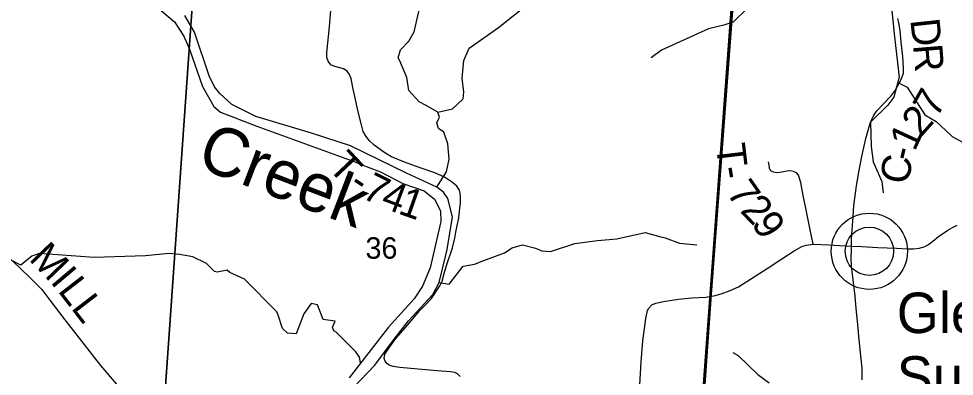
# Model space of a CAD drawing. Extents: x 1878108 to 2183446, y 146837 to 508383.
# Drawn here: x 2009743 to 2019382, y 343657 to 347340 of the extents above; entities that cross this region are included whole.
import ezdxf

# ---------------------------------------------------------------- set-up
doc = ezdxf.new("R2010")
doc.units = 0
for name, color, linetype in [('GM_X_County_Road', 7, 'Continuous'), ('GM_X_County_Road_Text', 7, 'Continuous'), ('GM_X_Major_River', 7, 'Continuous'), ('GM_X_Major_River_Text', 7, 'Continuous'), ('GM_X_Minor_River', 7, 'Continuous'), ('GM_X_Section', 7, 'Continuous'), ('GM_X_Section_Text', 7, 'Continuous'), ('GM_X_Township', 7, 'Continuous'), ('GM_X_Township_Road', 7, 'Continuous'), ('GM_X_Township_Road_Text', 7, 'Continuous'), ('GM_X_Unincorporated', 7, 'Continuous'), ('GM_X_Unincorporated_Location', 7, 'Continuous'), ('GM_X_Unincorporated_Text', 7, 'Continuous')]:
    doc.layers.add(name, color=color, linetype=linetype)

msp = doc.modelspace()

# ---------------------------------------------------------------- linework, layer by layer
at = {"layer": 'GM_X_County_Road'}
for points in [[(2018530.7, 346300.4), (2018548.9, 346340.2), (2018582.5, 346390.8), (2018650, 346461.6), (2018730.6, 346546.7), (2018771, 346602.2), (2018835.3, 346714.4), (2018858.1, 346779.8), (2018859.2, 346832.1), (2018852.7, 346949.7), (2018835.3, 347099), (2018823.3, 347215.6), (2018811.3, 347300.6), (2018799.3, 347342)], [(2018324.2, 344996.4), (2018323.2, 345071.3), (2018339.5, 345301.2), (2018347.1, 345415.6), (2018375.5, 345619.4), (2018398.3, 345761), (2018429.9, 345920.1), (2018470.3, 346107.5), (2018519.3, 346275.3), (2018530.7, 346300.4)], [(2018324.2, 344996.4), (2018427.8, 344992.8), (2018594.5, 344985.2), (2018787.3, 344977.6), (2018899.6, 344971), (2018961.7, 344970), (2019019.7, 344975.4), (2019072.5, 344991.2), (2019115.1, 345013.6), (2019161.2, 345048.4), (2019220.7, 345095.6), (2019315, 345160.7), (2019364.4, 345191), (2019410.4, 345212.3)], [(2016901.9, 344485.5), (2016904.6, 344486), (2016980.9, 344506.2), (2017071.8, 344539.8), (2017159.4, 344579.1), (2017463.7, 344774.5), (2017606.2, 344867.7), (2017733.7, 344949.3), (2017810, 344995), (2017856.8, 345008.1), (2017926.5, 345016.8), (2018088.9, 345012.4), (2018197.9, 345003.5), (2018324.2, 344996.4)], [(2009594.6, 344923.9), (2009753.8, 344775.2), (2009864.7, 344667.6), (2009981.3, 344549.9), (2010065.1, 344440.1), (2010219, 344237.5), (2010340.1, 344081.3), (2010523.5, 343845.9), (2010584.6, 343767.8), (2010746.5, 343578.8), (2010929.9, 343384.1), (2010998.9, 343310.5), (2011047.6, 343269.7), (2011211.7, 343195), (2011652, 343011.7), (2011765.8, 342960.5)], [(2016135.5, 343447.5), (2016149, 343684.4), (2016155.7, 343806.7), (2016171.5, 344023.4), (2016202.9, 344252.4), (2016219.7, 344334.4), (2016235.4, 344360.2), (2016264.6, 344391.6), (2016307.3, 344411.9), (2016385.9, 344428.7), (2016541.9, 344452.3), (2016677.8, 344464.6), (2016823.7, 344472.5), (2016875, 344481), (2016901.9, 344485.5)]]:
    msp.add_lwpolyline(points, dxfattribs=at)
at = {"layer": 'GM_X_Major_River'}
for points in [[(2010888.7, 347700.8), (2011346.8, 347309.5), (2011442.9, 347159.5), (2011503.1, 347027.4), (2011635.6, 346641.1), (2011753.8, 346437), (2011821.8, 346377.1), (2012195.6, 346232), (2013214.9, 345862.6), (2013276.8, 345836.7), (2013468.7, 345763.2), (2013698.6, 345643.7), (2013918.5, 345568.3), (2014026.5, 345480.5), (2014088.6, 345360.4), (2014092.8, 345250.2), (2013981.8, 344772.9), (2013904.2, 344584.3), (2013816.6, 344455.8), (2013553.4, 344162.4), (2013146.9, 343640.1)], [(2013119.3, 343467.7), (2013412.3, 343773.2), (2013609.6, 344040.3), (2013757.1, 344227.1), (2014008.2, 344498.5), (2014073.9, 344622.9), (2014139.4, 344889.6), (2014157.2, 344961.8), (2014212.5, 345300.7), (2014164.3, 345488.9), (2014118.2, 345554.9), (2014050.2, 345604.8), (2013738.4, 345750), (2013162.6, 346030.7), (2012758.9, 346159.7), (2012185.4, 346334.2), (2011939.5, 346455.7), (2011813.5, 346571.5), (2011759.4, 346637.5), (2011705.3, 346753.5), (2011552.7, 347199.9), (2011454.5, 347374)]]:
    msp.add_lwpolyline(points, dxfattribs=at)
at = {"layer": 'GM_X_Minor_River'}
for points in [[(2018025, 348200.1), (2017916.9, 347951.6), (2017891.1, 347835.4), (2017839.3, 347749.2), (2017611.7, 347612.6), (2017250.2, 347447.7), (2017102.6, 347303.2), (2017008.7, 347275), (2016850.9, 347234.7), (2016365.7, 347017.5), (2016257.9, 346937.2)], [(2014060.9, 346378.4), (2014210.7, 346412.7), (2014320.5, 346515.1), (2014330.4, 346583.1), (2014312.2, 346729.3), (2014328, 346909.5), (2014383.8, 347037.8), (2014687.2, 347250.6), (2015038.5, 347535.6), (2015148.3, 347666), (2015295.7, 348036.8)], [(2014050.2, 345604.8), (2014149.5, 345761.8), (2014179.3, 345892), (2014163.1, 346052.2), (2014121, 346172.3), (2014067.1, 346208.2), (2014051, 346266.2), (2014076.9, 346326.4), (2014060.9, 346378.4), (2013934.9, 346448.2), (2013867, 346484.2), (2013761, 346600.1), (2013742.8, 346734.2), (2013670.7, 346906.3), (2013652.7, 346938.3), (2013674.6, 347020.5), (2013760.4, 347108.7), (2013818.2, 347205), (2013865.9, 347413.3), (2013873.9, 347463.4), (2013883.6, 347671.6), (2013921.4, 347827.9)], [(2018627.8, 347657.6), (2018728.5, 347522.6), (2018764.9, 347154.2), (2018813.3, 346739.8), (2018759.6, 346533.5), (2018697.8, 346451.2), (2018518.2, 346274.7), (2018526.4, 346024.4), (2018546.6, 345866.3), (2018634.7, 345662.2), (2018648.8, 345546.1)], [(2018798.5, 346682.9), (2018895.4, 346633.8), (2019077.5, 346351.8), (2019193.4, 346280), (2019293.4, 346188.1), (2019359.4, 346126.1), (2019543.3, 346026.3), (2019723.4, 345774.4), (2019785.4, 345730.4), (2019815.4, 345702.5)], [(2014074.2, 344624), (2014176.7, 344606.6), (2014320.4, 344791.1), (2014440.2, 344813.3), (2014534.1, 344851.5), (2014747.8, 344928), (2014827.6, 344980.2), (2014933.5, 345012.5), (2015067.4, 344976.7), (2015131.3, 344950.8), (2015221.2, 344942.9), (2015470.9, 345025.5), (2015706.6, 345056), (2015906.3, 345074.4), (2016196, 345139), (2016359.8, 345095.2), (2016401.8, 345083.3), (2016549.7, 345029.5), (2016729.5, 345011.8)], [(2013265.4, 343795.9), (2013252.5, 343854), (2013216.5, 343910), (2013012.5, 344111.9), (2012988.5, 344123.8), (2012976.5, 344161.9), (2013002.4, 344224), (2012878.5, 344241.8), (2012822.4, 344393.8), (2012756.5, 344405.7), (2012678.7, 344299.5), (2012601, 344093.1), (2012511.1, 344102.9), (2012461.1, 344150.9), (2012417, 344287), (2012402.9, 344321), (2012068.9, 344658.7), (2011919, 344724.5), (2011889, 344750.5), (2011789.1, 344728.3), (2011761.2, 344736.2), (2011679.2, 344818.1), (2011537.2, 344888), (2011399.4, 344911.7), (2011291.5, 344923.5), (2011049.8, 344897.1), (2010520.3, 344882.1), (2009954.9, 344921), (2009877, 344894.9), (2009805.1, 344836.7), (2009763.2, 344800.6), (2009535.3, 344918.3)], [(2017101.6, 343900.5), (2017153.8, 343870.5), (2017358.5, 343674.5), (2017472.9, 343588.5)]]:
    msp.add_lwpolyline(points, dxfattribs=at)
at = {"layer": 'GM_X_Section'}
for points in [[(2011587.2, 348298.2), (2011214.3, 342968.4), (2006158.5, 343339.8), (2005874.4, 343365.2), (2006273.3, 348657.1)], [(2017121.1, 347933.9), (2017107.5, 347769.8), (2016724.2, 342600), (2011392.3, 342956.8), (2011214.3, 342968.4), (2011587.2, 348298.2)], [(2022491.3, 347433.1), (2022076.7, 341977.1), (2016695, 342231.8), (2016724.2, 342600), (2017107.5, 347769.8)]]:
    msp.add_lwpolyline(points, close=True, dxfattribs=at)
at = {"layer": 'GM_X_Township'}
for points in [[(2022085.4, 341976.5), (2018357.7, 342153.1), (2017167.6, 342204.4), (2016711.2, 342233), (2016735.7, 342465.3), (2016771.3, 342980.5), (2016876.3, 344500.5), (2017298, 350114.1), (2017363.4, 350984.7), (2017639.3, 354834.1), (2017696.9, 355615), (2017915.9, 358580.9), (2018284.3, 364566.1), (2018295.1, 364714.1), (2018544, 369044.3), (2019393.9, 369074.7)], [(2017298, 350114.1), (2016876.3, 344500.5), (2016771.3, 342980.5), (2016735.7, 342465.3), (2014090.7, 342780.8), (2012240.2, 342898.1), (2008693, 343157.7), (2004354.1, 343457.5), (2003141.6, 343548.2), (2000896.9, 343716.1), (1999693.4, 343807.9), (1997660.6, 343962.9), (1995715.1, 344111.2), (1994970.8, 344177.4), (1990310.6, 344542.4), (1989690.7, 344598.5), (1988327.1, 344706.4), (1984472.4, 345011.3), (1984423, 345015.2), (1984436.4, 345172.5), (1984507.3, 345999.8), (1984847.2, 350030.1)]]:
    msp.add_lwpolyline(points, dxfattribs=at)
at = {"layer": 'GM_X_Township_Road'}
for points in [[(2014292.4, 343655.4), (2014263.8, 343684), (2014235.2, 343695.6), (2014190.6, 343703.6), (2014053.9, 343712.6), (2013821.6, 343734), (2013669.7, 343749.2), (2013600.1, 343759), (2013559, 343771.5), (2013536.6, 343789.4), (2013517.7, 343813.3), (2013508, 343842.1), (2013515.2, 343885.9), (2013553.6, 343941.3), (2013590.2, 343994.9), (2013632.2, 344048.5), (2013748.4, 344185.1), (2013874.3, 344335.2), (2013927.9, 344387.9), (2013996.7, 344456.7), (2014079.8, 344589.8), (2014104.2, 344635.3), (2014127.7, 344717), (2014153.9, 344808.7), (2014212, 344979.3), (2014236.7, 345079.1), (2014246.8, 345142.8), (2014259.3, 345209.8), (2014278.1, 345287.5), (2014285.3, 345359), (2014295.1, 345444.8), (2014295.1, 345502.8), (2014291.5, 345543), (2014282.6, 345572.5), (2014256.7, 345614.5), (2014212.9, 345654.7), (2014129.8, 345707.4), (2014028.9, 345751.2), (2013869.9, 345807.5), (2013717.1, 345861.1), (2013584, 345917.3), (2013514.3, 345958.4), (2013404.4, 346037), (2013353.5, 346087.1), (2013315.1, 346136.2), (2013291, 346178.2), (2013274, 346248.8), (2013238.3, 346394.4), (2013213.2, 346507.8), (2013186.4, 346630.2), (2013169.5, 346724), (2013149.8, 346766.9), (2013128.4, 346798.2), (2013090, 346822.3), (2012999.7, 346848.2), (2012958.6, 346864.3), (2012930.9, 346901.8), (2012917.5, 346941.1), (2012915.8, 346993.8), (2012944.3, 347255.6), (2012961.3, 347469.1)], [(2017926.5, 345016.8), (2017893.7, 345183.1), (2017851, 345389.7), (2017826.3, 345517.7), (2017800.5, 345654.7), (2017778, 345727.6), (2017756.7, 345753.5), (2017724.1, 345768.1), (2017694.9, 345772.6), (2017657.9, 345770.3), (2017604, 345761.3), (2017552.4, 345752.3), (2017518.7, 345758), (2017491.7, 345772.6), (2017478.3, 345796.1), (2017474.9, 345834.3), (2017469.3, 345864.6)], [(2018433.5, 343621.2), (2018432.3, 343741.1), (2018419.4, 343868), (2018398.2, 344065.5), (2018391, 344157), (2018371.9, 344356.8), (2018361.3, 344484), (2018340.6, 344650.7), (2018323.2, 344792.4), (2018318.8, 344876.3), (2018323.2, 344954.7), (2018324.2, 344996.4)]]:
    msp.add_lwpolyline(points, dxfattribs=at)
at = {"layer": 'GM_X_Unincorporated'}
for radius in [392.8, 249]:
    msp.add_circle((2018506.7, 344944.8), radius, dxfattribs=at)
at = {"layer": 'GM_X_Unincorporated_Location'}
msp.add_line((2018506.7, 344944.8), (2018506.7, 344944.8), dxfattribs=at)

# ---------------------------------------------------------------- texts
at = {"layer": 'GM_X_County_Road_Text'}
for s, rotation, p in [('D', 276.28549, (2018927.7, 347329.1)), ('R', 274.82977, (2018956.4, 347068.7)), ('7', 60.61429, (2019201.1, 346308.8)), ('2', 48.4611, (2019038.3, 346114)), ('1', 65.19469, (2018973.4, 345965.5)), ('-', 76.53553, (2018949.8, 345860.5)), ('C', 79.14321, (2018904.2, 345622.1)), ('M', 313.83871, (2009838.3, 344860)), ('I', 310.27533, (2010060.5, 344628.9)), ('L', 307.75189, (2010138, 344537.6)), ('L', 307.56246, (2010275.2, 344360.3))]:
    msp.add_text(s, height=300, rotation=rotation, dxfattribs=at).set_placement(p)
at = {"layer": 'GM_X_Major_River_Text'}
msp.add_text('Creek', height=499.98, rotation=339.00255, dxfattribs=at).set_placement((2011558, 345820))
at = {"layer": 'GM_X_Section_Text'}
msp.add_text('36', height=221, rotation=0.00001, dxfattribs=at).set_placement((2013315.6, 344868.2))
at = {"layer": 'GM_X_Township_Road_Text'}
for s, rotation, p in [('T', 276.81725, (2016925.6, 346039.6)), ('T', 313.22841, (2012917.9, 345802.7)), ('7', 332.98435, (2013263.9, 345503.5)), ('-', 279.20556, (2016954.1, 345803.3)), ('-', 326.31538, (2013128.5, 345591)), ('7', 305.05782, (2017029, 345546.1)), ('4', 339.10523, (2013460.4, 345405.4)), ('1', 340.55859, (2013640.9, 345336.6)), ('2', 313.75742, (2017166.6, 345356.5)), ('9', 302.23211, (2017284.6, 345235.6))]:
    msp.add_text(s, height=300, rotation=rotation, dxfattribs=at).set_placement(p)
at = {"layer": 'GM_X_Unincorporated_Text'}
for s, p in [('Glen', (2018789.2, 344102.1)), ('Summitt', (2018789.2, 343446.5))]:
    msp.add_text(s, height=417, rotation=0.00001, dxfattribs=at).set_placement(p)

doc.saveas('drawing.dxf')
